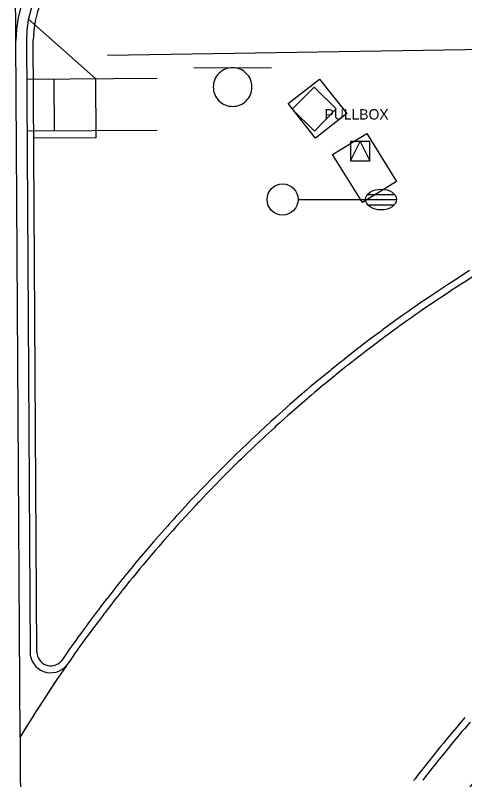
# Model space of a CAD drawing. Extents: x 2145380 to 2157287, y 139568 to 149130.
# Drawn here: x 2150890.7 to 2150934.1, y 148158 to 148231.8 of the extents above; entities that cross this region are included whole.
import ezdxf

# ---------------------------------------------------------------- set-up
doc = ezdxf.new("R2010")
doc.units = 0
for name, color, linetype in [('Default', 7, 'Continuous'), ('PR_PREVIOUSLY CONSTRUCTED', 7, 'Continuous'), ('TOPO_Concrete', 7, 'Continuous'), ('TOPO_Light Pole', 7, 'Continuous'), ('TOPO_Misc', 7, 'Continuous'), ('TOPO_Power Pullbox', 7, 'Continuous'), ('TOPO_Sidewalk', 7, 'Continuous'), ('TOPO_Sign', 7, 'Continuous')]:
    doc.layers.add(name, color=color, linetype=linetype)

# ---------------------------------------------------------------- blocks, each defined once
blk = doc.blocks.new('LP')
at = {"layer": 'TOPO_Light Pole'}
blk.add_line((3.81, 0), (20.32, 0), dxfattribs=at)
for points in [[(20.32, 0), (27.94, 0)], [(20.32, 0), (23.5, 0)], [(20.83, 1.27), (27.43, 1.27)], [(20.83, 1.27), (23.5, 1.27)], [(23.71, 1.27), (27.43, 1.27)], [(23.71, 0), (27.94, 0)], [(20.83, -1.27), (27.43, -1.27)], [(20.83, -1.27), (23.5, -1.27)], [(23.71, -1.27), (27.43, -1.27)]]:
    blk.add_lwpolyline(points, dxfattribs=at)
blk.add_circle((0, 0), 3.81, dxfattribs=at)
blk.add_ellipse((24.13, 0), major_axis=(3.81, 0), ratio=0.666667, dxfattribs=at)
blk = doc.blocks.new('pulbox')
at = {"layer": 'Default'}
blk.add_lwpolyline([(-5.38, -0.01), (-0.02, 5.42), (5.4, 0.06), (0.05, -5.36), (-5.38, -0.01)], dxfattribs=at)
blk.add_text('PULLBOX', height=2.54, dxfattribs=at).set_placement((2.54, -2.54))

msp = doc.modelspace()

# ---------------------------------------------------------------- linework, layer by layer
at = {"layer": 'PR_PREVIOUSLY CONSTRUCTED'}
for p, q in [((2150891.218, 148162.164), (2150890.814, 148229.33)), ((2150891.814, 148229.336), (2150892.168, 148170.352)), ((2150892.835, 148170.356), (2150892.481, 148229.34)), ((2150904.418, 148225.672), (2150891.836, 148225.596)), ((2150894.533, 148220.612), (2150894.503, 148225.612)), ((2150898.537, 148219.969), (2150898.503, 148225.636)), ((2150904.448, 148220.672), (2150891.867, 148220.596)), ((2150898.537, 148219.969), (2150892.537, 148219.933))]:
    msp.add_line(p, q, dxfattribs=at)
for points in [[(2150890.814, 148229.33), (2150890.748, 148240.31)], [(2150892.017, 148231.403), (2150898.503, 148225.636)], [(2150934.569, 148207.145), (2150933.712, 148206.602), (2150933.641, 148206.557), (2150933.499, 148206.466), (2150932.434, 148205.777), (2150932.425, 148205.771), (2150931.376, 148205.077), (2150931.311, 148205.034), (2150931.147, 148204.924), (2150930.323, 148204.367), (2150929.878, 148204.063), (2150929.277, 148203.647), (2150929.011, 148203.462), (2150928.618, 148203.187), (2150928.236, 148202.917), (2150927.367, 148202.296), (2150927.202, 148202.177), (2150926.74, 148201.841), (2150926.175, 148201.427), (2150926.125, 148201.39), (2150925.154, 148200.666), (2150924.893, 148200.469), (2150924.501, 148200.172), (2150924.14, 148199.896), (2150923.671, 148199.535), (2150923.132, 148199.116), (2150922.458, 148198.585), (2150922.295, 148198.456), (2150922.132, 148198.326), (2150921.256, 148197.622), (2150921.138, 148197.526), (2150920.152, 148196.717), (2150920.122, 148196.692), (2150920.064, 148196.645), (2150919.173, 148195.898), (2150918.883, 148195.653), (2150918.201, 148195.07), (2150917.984, 148194.882), (2150917.713, 148194.648), (2150917.236, 148194.232), (2150916.553, 148193.628), (2150916.279, 148193.384), (2150915.881, 148193.027), (2150915.405, 148192.595), (2150915.33, 148192.528), (2150914.389, 148191.662), (2150914.267, 148191.549), (2150913.816, 148191.127), (2150913.455, 148190.786), (2150913.142, 148190.489), (2150912.529, 148189.902), (2150912.027, 148189.416), (2150911.789, 148189.183), (2150911.611, 148189.009), (2150910.925, 148188.33), (2150910.702, 148188.106), (2150909.835, 148187.231), (2150909.8, 148187.195), (2150909.8, 148187.195), (2150908.907, 148186.275), (2150908.757, 148186.118), (2150908.022, 148185.347), (2150907.852, 148185.166), (2150907.691, 148184.994), (2150907.146, 148184.409), (2150906.637, 148183.856), (2150906.279, 148183.463), (2150905.945, 148183.094), (2150905.596, 148182.706), (2150905.42, 148182.509), (2150904.57, 148181.546), (2150904.568, 148181.544), (2150904.08, 148180.982), (2150903.729, 148180.575), (2150903.553, 148180.37), (2150902.897, 148179.596), (2150902.552, 148179.184), (2150902.258, 148178.831), (2150902.074, 148178.608), (2150901.563, 148177.986), (2150901.26, 148177.613), (2150900.588, 148176.776), (2150900.48, 148176.64), (2150900.455, 148176.609), (2150899.66, 148175.598), (2150899.626, 148175.555), (2150898.874, 148174.579), (2150898.772, 148174.446), (2150898.746, 148174.412), (2150898.679, 148174.323), (2150898.097, 148173.552), (2150897.745, 148173.079), (2150897.331, 148172.518), (2150897.059, 148172.147), (2150896.825, 148171.825), (2150896.573, 148171.476), (2150895.919, 148170.559), (2150895.826, 148170.427), (2150895.418, 148169.846), (2150895.159, 148169.472)], [(2150934.924, 148206.58), (2150934.071, 148206.04), (2150934, 148205.994), (2150933.859, 148205.904), (2150932.8, 148205.218), (2150932.791, 148205.212), (2150931.746, 148204.522), (2150931.682, 148204.479), (2150931.519, 148204.37), (2150930.699, 148203.816), (2150930.256, 148203.513), (2150929.658, 148203.099), (2150929.393, 148202.915), (2150929.002, 148202.641), (2150928.622, 148202.372), (2150927.757, 148201.754), (2150927.594, 148201.636), (2150927.134, 148201.302), (2150926.571, 148200.889), (2150926.521, 148200.853), (2150925.555, 148200.133), (2150925.295, 148199.937), (2150924.906, 148199.641), (2150924.546, 148199.366), (2150924.079, 148199.007), (2150923.544, 148198.59), (2150922.873, 148198.062), (2150922.71, 148197.933), (2150922.548, 148197.804), (2150921.677, 148197.103), (2150921.559, 148197.008), (2150920.578, 148196.203), (2150920.548, 148196.178), (2150920.491, 148196.131), (2150919.603, 148195.388), (2150919.315, 148195.144), (2150918.636, 148194.564), (2150918.42, 148194.377), (2150918.151, 148194.144), (2150917.677, 148193.73), (2150916.997, 148193.129), (2150916.724, 148192.886), (2150916.328, 148192.531), (2150915.854, 148192.101), (2150915.78, 148192.034), (2150914.843, 148191.172), (2150914.722, 148191.06), (2150914.273, 148190.64), (2150913.914, 148190.301), (2150913.602, 148190.006), (2150912.992, 148189.421), (2150912.493, 148188.938), (2150912.256, 148188.706), (2150912.079, 148188.533), (2150911.396, 148187.857), (2150911.174, 148187.635), (2150910.311, 148186.763), (2150910.277, 148186.728), (2150910.277, 148186.728), (2150909.388, 148185.813), (2150909.239, 148185.656), (2150908.508, 148184.888), (2150908.338, 148184.708), (2150908.178, 148184.537), (2150907.636, 148183.956), (2150907.13, 148183.405), (2150906.773, 148183.014), (2150906.441, 148182.647), (2150906.094, 148182.261), (2150905.918, 148182.065), (2150905.073, 148181.107), (2150905.071, 148181.105), (2150904.585, 148180.546), (2150904.236, 148180.14), (2150904.061, 148179.936), (2150903.407, 148179.166), (2150903.064, 148178.756), (2150902.772, 148178.405), (2150902.588, 148178.183), (2150902.08, 148177.564), (2150901.779, 148177.193), (2150901.11, 148176.36), (2150901.002, 148176.225), (2150900.978, 148176.194), (2150900.186, 148175.188), (2150900.153, 148175.145), (2150899.404, 148174.174), (2150899.303, 148174.041), (2150899.278, 148174.007), (2150899.21, 148173.919), (2150898.632, 148173.152), (2150898.281, 148172.681), (2150897.869, 148172.123), (2150897.599, 148171.753), (2150897.366, 148171.433), (2150897.115, 148171.086), (2150896.465, 148170.174), (2150896.372, 148170.042), (2150895.966, 148169.464), (2150895.638, 148168.991), (2150895.578, 148168.904), (2150894.914, 148167.932), (2150894.705, 148167.624), (2150894.381, 148167.14), (2150894.377, 148167.134), (2150894.2, 148166.867), (2150893.847, 148166.333), (2150893.495, 148165.795), (2150893.004, 148165.033), (2150892.844, 148164.782), (2150892.801, 148164.715), (2150892.176, 148163.723), (2150892.118, 148163.629), (2150891.444, 148162.537), (2150891.362, 148162.403), (2150891.355, 148162.391), (2150891.211, 148162.153), (2150891.209, 148162.15), (2150891.213, 148161.186), (2150891.216, 148160.698), (2150891.222, 148159.716), (2150891.225, 148159.239), (2150891.227, 148158.93), (2150891.231, 148158.26), (2150891.238, 148157.182)], [(2150895.691, 148169.068), (2150895.578, 148168.904), (2150894.914, 148167.932), (2150894.543, 148167.382), (2150894.023, 148166.6), (2150893.495, 148165.795), (2150892.801, 148164.715), (2150892.489, 148164.219), (2150892.118, 148163.629), (2150891.781, 148163.083), (2150891.444, 148162.537), (2150891.444, 148162.537), (2150891.403, 148162.47), (2150891.355, 148162.391), (2150891.283, 148162.272), (2150891.218, 148162.164)], [(2150934.113, 148164.035), (2150933.57, 148163.406), (2150933.444, 148163.259), (2150933.325, 148163.119), (2150932.923, 148162.644), (2150932.546, 148162.195), (2150932.281, 148161.877), (2150932.035, 148161.578), (2150931.777, 148161.264), (2150931.647, 148161.104), (2150931.018, 148160.326), (2150931.017, 148160.325), (2150930.656, 148159.871), (2150930.396, 148159.543), (2150930.267, 148159.378), (2150929.781, 148158.755), (2150929.526, 148158.424), (2150929.309, 148158.14), (2150929.172, 148157.961)], [(2150934.618, 148163.596), (2150934.079, 148162.97), (2150933.953, 148162.824), (2150933.835, 148162.685), (2150933.435, 148162.213), (2150933.061, 148161.766), (2150932.797, 148161.45), (2150932.552, 148161.152), (2150932.296, 148160.84), (2150932.166, 148160.681), (2150931.541, 148159.908), (2150931.54, 148159.906), (2150931.181, 148159.455), (2150930.923, 148159.129), (2150930.794, 148158.965), (2150930.311, 148158.345), (2150930.057, 148158.016)]]:
    msp.add_lwpolyline(points, dxfattribs=at)
for centre, radius, start, end in [((2150901.814, 148229.396), 11, 90.44677, 180.34426), ((2150901.814, 148229.396), 10, 90.44677, 180.34426), ((2150901.814, 148229.396), 9.333, 90.44677, 180.34426), ((2151024.682, 148085.312), 115.333, 90.25913, 180.34425), ((2150894.168, 148170.364), 2, 180.34426, 319.58599), ((2150894.168, 148170.364), 1.333, 180.34426, 317.96875)]:
    msp.add_arc(centre, radius, start, end, dxfattribs=at)
at = {"layer": 'TOPO_Concrete'}
for points in [[(2150919.712, 148219.928), (2150917.084, 148223.256), (2150920.088, 148225.628), (2150922.716, 148222.3), (2150919.712, 148219.928)], [(2150924.641, 148220.381), (2150927.516, 148215.752), (2150924.232, 148213.711), (2150921.356, 148218.34), (2150924.641, 148220.381)]]:
    msp.add_lwpolyline(points, dxfattribs=at)
at = {"layer": 'TOPO_Misc'}
msp.add_lwpolyline([(2150923.084, 148217.744), (2150924.955, 148217.748), (2150924.952, 148219.619), (2150923.08, 148219.616), (2150923.084, 148217.744), (2150924.018, 148219.616), (2150924.955, 148217.748)], dxfattribs=at)
at = {"layer": 'TOPO_Sidewalk'}
msp.add_lwpolyline([(2150899.652, 148227.927), (2150974.733, 148229.127), (2151033.887, 148230.058)], dxfattribs=at)
at = {"layer": 'TOPO_Sign'}
for points in [[(2150907.96, 148226.723), (2150915.453, 148226.73)], [(2150911.71, 148226.723), (2150911.71, 148226.723)], [(2150909.842, 148224.855), (2150909.842, 148224.855)], [(2150913.578, 148224.855), (2150913.578, 148224.855)], [(2150911.71, 148222.987), (2150911.71, 148222.987)]]:
    msp.add_lwpolyline(points, dxfattribs=at)
for start, end in [(89.99996, 180.00004), (359.99996, 90.00004), (179.99996, 270.00004), (269.99996, 0.00004)]:
    msp.add_arc((2150911.71, 148224.855), 1.868, start, end, dxfattribs=at)

# ---------------------------------------------------------------- block references
at = {"layer": 'TOPO_Light Pole', "xscale": 0.39370000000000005, "yscale": 0.3937000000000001}
msp.add_blockref('LP', (2150916.53, 148214.007), dxfattribs=at)
at = {"layer": 'TOPO_Power Pullbox', "xscale": 0.39370000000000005, "yscale": 0.3937000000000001}
msp.add_blockref('pulbox', (2150919.584, 148222.722), dxfattribs=at)

doc.saveas('drawing.dxf')
